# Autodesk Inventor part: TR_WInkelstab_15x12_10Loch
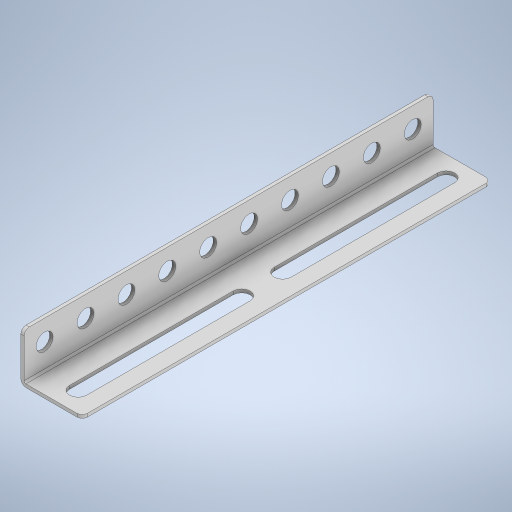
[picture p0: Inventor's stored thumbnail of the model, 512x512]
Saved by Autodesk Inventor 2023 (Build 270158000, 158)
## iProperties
Created: 2023-11
Part Number: TR_WInkelstab_15x12_10Loch
Material: Generisch
Document SubType Name: Modeling
Designer: Administrator
Density: 1 g/cm^3
Appearance: Vorgabe
Author: Administrator
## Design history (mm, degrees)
sketch "Skizze1"
  geometry: L1 (0, 12)-(0, 1.25); L2 (1.25, 0)-(15, 0); L3 (15, 0)-(15, 0.8); L4 (15, 0.8)-(1.25, 0.8); L5 (0.8, 1.25)-(0.8, 12); L6 (0.8, 12)-(0, 12); A1 r 1.25 centre (1.25, 1.25) between (0, 1.25) and (1.25, 0); A2 r 0.45 centre (1.25, 1.25) between (0.8, 1.25) and (1.25, 0.8); 1 further point
  constraints: 12 end point, 5 perpendicular, 4 point on circle, 4 tangent, 2 centre point, 2 point on line, 1 coincident, 1 vertical
  dimensions: "d0" = 1.25 radius of A1; "d2" = 0.8 distance of L5.end L1.start (= Dicke); "d3" = 12 distance of point (0, 0) L1.start; "d4" = 15 distance of point (0, 0) L2.end
extrude "Extrusion1" new body sketch "Skizze1" stored distance "d5" = 100 (computed from Lochzahl, Einheitsmaß); taper "d6" = 0 deg
sketch "Skizze2"
  geometry: L1 (7.75, 5)-(7.75, 45); L2 (9.825, 5)-(9.825, 45); L3 (5.675, 45)-(5.675, 5); L4 (13.75, 100)-(13.75, 0) reference; L5 (13.75, 0)-(0, 0) reference; A1 r 2.075 centre (7.75, 5) between (5.675, 5) and (9.825, 5); A2 r 2.075 centre (7.75, 45) between (9.825, 45) and (5.675, 45); 3 further points
  constraints: 8 end point, 4 point on circle, 4 tangent, 2 centre point, 2 midpoint, 1 parallel, 1 vertical
  dimensions: "d8" = 4.15 diameter of A2 (= 2 x Radius); "d9" = 40 distance of L1.start L1.end (= Langloch); "d10" = 6 distance from line of L4 L1.start; "d11" = 5 vertical distance of point (6.875, 0) L1.start (= 0.5 x Einheitsmaß)
extrude "Extrusion2" cut sketch "Skizze2" extent not by distance; stored distance "d12" = 0; taper "d13" = 0 deg
mirror "Spiegeln1"
sketch "Skizze3"
  geometry: L1 (0, 10.75)-(100, 10.75) reference; L2 (0, 0)-(0, 10.75) reference; C1 r 2.075 at (5, 5.75); 1 further point
  constraints: 1 centre point
  dimensions: "d14" = 4.15 diameter of C1 (= 2 x Radius); "d15" = 5 distance from line of C1.centre L1 (= 0.5 x Einheitsmaß); "d16" = 5 distance from line of C1.centre L2 (= 0.5 x Einheitsmaß)
extrude "Extrusion3" cut sketch "Skizze3" extent not by distance; stored distance "d17" = 0; taper "d18" = 0 deg
pattern_linear "Rechteckige Anordnung1" dims "d21" = 10 (= Einheitsmaß)
fillet "Rundung1" dims "d22" = 1.25
node "Volumenkörper1"
other parameters: "Einheitsmaß" = 10 [user parameter; used in 5 equation terms], "Radius" = 2.075 [user parameter; used in 2 equation terms], "Fasen" = 0.5 [user parameter], "Dicke" = 0.8 [user parameter; used in 1 equation term], "Breitloch" = 2 [user parameter], "Langloch" = 40 [user parameter; used in 1 equation term], "AchteckUmkreis" = 6 [user parameter], "DAchsAufnahme" = 4.1 [user parameter], "AchsDurchmesser" = 4 [user parameter], "AchsFase" = 0.5 [user parameter]
